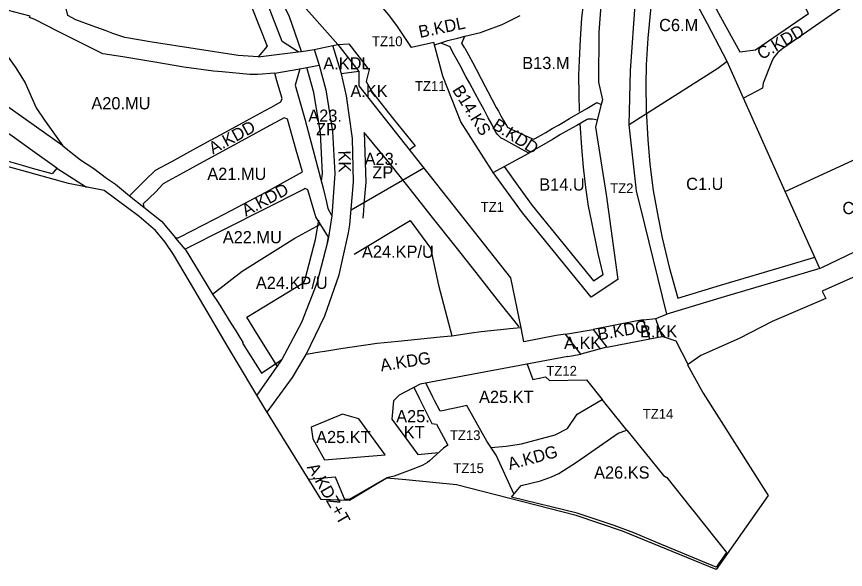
# Model space of a CAD drawing. Extents: x -292612 to -290407, y 29458 to 30862.
# Drawn here: x -292209 to -291531, y 29458 to 29911 of the extents above; entities that cross this region are included whole.
import ezdxf

# ---------------------------------------------------------------- set-up
doc = ezdxf.new("R2010")
doc.units = 0
for name, color, linetype in [('linie_rozgraniczajace', 7, 'Continuous'), ('linie_zabudowy_nieprzekraczalne', 7, 'Continuous'), ('linie_zabudowy_obowiazujace', 7, 'Continuous'), ('oznaczenia_przeznaczen', 7, 'Continuous')]:
    doc.layers.add(name, color=color, linetype=linetype)

msp = doc.modelspace()

# ---------------------------------------------------------------- linework, layer by layer
at = {"layer": 'linie_rozgraniczajace'}
for p, q in [((-291812.1, 29904.25), (-291797.36, 29911.59)), ((-291829.65, 29897.7), (-291825.32, 29899.4)), ((-291825.32, 29899.4), (-291812.1, 29904.25)), ((-291844.92, 29889.06), (-291842.53, 29894.59)), ((-291842.53, 29894.59), (-291829.65, 29897.7)), ((-291965.84, 29883.72), (-291950.47, 29887.05)), ((-291867.39, 29887.64), (-291862.03, 29889.28)), ((-291862.03, 29889.28), (-291854.9, 29886.32)), ((-291851.23, 29879.5), (-291854.9, 29886.32)), ((-291842.44, 29884.74), (-291844.92, 29889.06)), ((-292011.57, 29877.83), (-291978.9, 29881.84)), ((-291975.93, 29882.22), (-291965.84, 29883.72)), ((-291614.65, 29844.03), (-291628.04, 29874)), ((-291997.89, 29864.27), (-291977.45, 29868.02)), ((-291977.45, 29868.02), (-291961.66, 29870.95)), ((-291929.15, 29865.82), (-291943.39, 29863.71)), ((-292171.12, 29805.01), (-292230.27, 29846.8)), ((-291580.53, 29767.68), (-291614.65, 29844.03)), ((-292204.65, 29784.63), (-292279.28, 29805.58)), ((-291819.45, 29783.2), (-291790.26, 29798.92)), ((-292166.46, 29774.12), (-292204.65, 29784.63)), ((-292176.13, 29786.65), (-292151.9, 29771.21)), ((-292137.34, 29768.3), (-292166.46, 29774.12)), ((-292108.8, 29747.12), (-292137.34, 29768.3)), ((-292116.7, 29764.04), (-292105.11, 29754.82)), ((-291552.37, 29704.65), (-291580.53, 29767.68)), ((-292095.49, 29735.63), (-292108.8, 29747.12)), ((-291419.51, 29744.27), (-291550.37, 29686.12)), ((-292087.4, 29726.18), (-292095.49, 29735.63)), ((-292071.14, 29720.41), (-292079.07, 29729.79)), ((-291954.76, 29726.01), (-291953.92, 29730.34)), ((-292080.74, 29716.04), (-292087.4, 29726.18)), ((-292063.2, 29686.48), (-292080.74, 29716.04)), ((-292035.67, 29639.74), (-292063.2, 29686.48)), ((-291550.37, 29686.12), (-291547.48, 29680.03)), ((-291547.48, 29680.03), (-291591.32, 29661.25)), ((-291696.77, 29662.51), (-291686.12, 29663.74)), ((-291591.32, 29661.25), (-291618.23, 29647.39)), ((-291760.33, 29650.81), (-291737.71, 29654.77)), ((-291691.29, 29647.01), (-291681.18, 29648.88)), ((-291618.23, 29647.39), (-291649.65, 29633.45)), ((-292006.18, 29590.14), (-292035.67, 29639.74)), ((-291726.59, 29640.12), (-291747.55, 29634.63)), ((-291992.84, 29629.15), (-291992.27, 29630.09)), ((-291649.65, 29633.45), (-291660.43, 29625.85)), ((-291660.43, 29625.85), (-291647.77, 29602.64)), ((-291742.98, 29613.44), (-291730.19, 29597.44)), ((-291647.77, 29602.64), (-291594.44, 29518.94)), ((-291710.19, 29572.46), (-291730.19, 29597.44)), ((-291960, 29515.62), (-292006.18, 29590.14)), ((-291912.73, 29529.27), (-291936.78, 29514.91)), ((-291906.28, 29532.99), (-291912.73, 29529.27)), ((-291890.88, 29531.71), (-291906.28, 29532.99)), ((-291849.33, 29527.56), (-291890.88, 29531.71)), ((-291751.47, 29502.66), (-291849.33, 29527.56)), ((-291936.78, 29514.91), (-291960, 29515.62)), ((-291594.44, 29518.94), (-291636.96, 29458.4)), ((-291713.73, 29489.82), (-291751.47, 29502.66)), ((-291636.96, 29458.4), (-291713.73, 29489.82))]:
    msp.add_line(p, q, dxfattribs=at)
for points in [[(-292114.36, 30097.25), (-292083.21, 30056.76), (-292057.73, 30024.34), (-292038.64, 30000), (-292027.25, 29985.48), (-292000, 29950.73), (-291986.69, 29933.75), (-291946.41, 29887.93)], [(-291978.9, 29881.84), (-291991.76, 29890.16), (-292004.47, 29922.77), (-292020.82, 29953.71), (-292040.59, 29982.6), (-292063.52, 30009.04), (-292089.32, 30032.69), (-292097.85, 30039.41), (-292114.29, 30050.9), (-292134.97, 30069.53), (-292134, 30082.58), (-292121.07, 30092.24), (-292116.85, 30090.65)], [(-291975.93, 29882.22), (-291986.13, 29911.24), (-291999.65, 29938.08), (-292000.85, 29939.93), (-292019.3, 29969.25), (-292074.88, 30038.31), (-292089.02, 30055.89), (-292116.85, 30090.65)], [(-292166.99, 29911.62), (-292169.08, 29919.34), (-292154.75, 29958), (-292118.26, 30025.98), (-292105.47, 30028.88), (-292100.59, 30025.07), (-292075.06, 30002.23), (-292052.38, 29976.58), (-292032.83, 29948.45), (-292016.7, 29918.24), (-292004.2, 29886.35), (-292011.57, 29877.83)], [(-291669.49, 29987.68), (-291671.27, 29980.66), (-291633.48, 29910.49), (-291617.58, 29881.84), (-291604.81, 29883.45), (-291561.59, 29913.3), (-291592.04, 29971.03), (-291613.04, 30015.42), (-291620.76, 30015.91)], [(-291628.04, 29874), (-291644.01, 29904.73), (-291682.1, 29975.46), (-291688.74, 29976.95)], [(-291708.15, 29822.07), (-291707.18, 29866.32), (-291703.04, 29924.32), (-291698.38, 29961.89), (-291704.52, 29968.14)], [(-291729.07, 29948.78), (-291732.96, 29897.85), (-291733.22, 29856.93), (-291730.07, 29842.68), (-291731.09, 29838.65)], [(-291477.58, 29947.7), (-291488.85, 29948.52), (-291538.79, 29914.86), (-291582.58, 29884.55), (-291586.65, 29881.17), (-291590.07, 29876.95), (-291591.84, 29873.31), (-291598.51, 29856.15), (-291599.12, 29852.22), (-291614.65, 29844.03)], [(-292176.13, 29786.65), (-292196.11, 29800.91), (-292210.7, 29811.42), (-292226.79, 29822.79), (-292241.71, 29833.57), (-292257.21, 29844.57), (-292269.58, 29853.38), (-292281.3, 29861.8), (-292295.02, 29871.61), (-292309.25, 29881.48), (-292327.43, 29894.85), (-292343.8, 29906.62), (-292364.93, 29920.68), (-292373.24, 29925.15), (-292378.63, 29927), (-292388.33, 29930.59), (-292395.2, 29933), (-292403.59, 29934.7), (-292409.88, 29935.52), (-292417.09, 29936.06)], [(-291819.45, 29783.2), (-291820.74, 29785.22), (-291845.84, 29824.54), (-291860.59, 29861.86), (-291867.85, 29889.42), (-291886.03, 29885.5), (-291897.71, 29902.45), (-291904.57, 29912.13), (-291917.59, 29927.44), (-291924.51, 29934.99)], [(-291997.89, 29864.27), (-292011.86, 29863.38), (-292018.37, 29863.29), (-292040.84, 29865.39), (-292047.97, 29865.95), (-292072.31, 29869.28), (-292095.86, 29873.28), (-292122.04, 29877.72), (-292138.55, 29880.13), (-292175.49, 29898.85), (-292194.21, 29908.17), (-292198.39, 29909.92), (-292198.03, 29911.14), (-292216.69, 29915.79), (-292234.71, 29910.07), (-292238.43, 29904.69), (-292222.57, 29886.61), (-292209.52, 29868.85), (-292202.01, 29856.35), (-292193.02, 29835.97), (-292186.08, 29825.88), (-292171.12, 29805.01)], [(-292011.57, 29877.83), (-292027.9, 29878.97), (-292098.18, 29889.69), (-292120.57, 29893.65), (-292130.23, 29896.77), (-292135.79, 29898.9), (-292147.1, 29903), (-292160.49, 29907.99), (-292166.99, 29911.62)], [(-291862.03, 29889.28), (-291856.29, 29891.03), (-291847.39, 29893.41), (-291842.53, 29894.59)], [(-292004.27, 29587.05), (-291983.42, 29615.52), (-291972.23, 29634.18), (-291956.92, 29665.97), (-291945.31, 29699.29), (-291937.53, 29733.71), (-291936.49, 29740.42), (-291933.42, 29775.57), (-291934.36, 29810.85), (-291939.27, 29845.79), (-291943.39, 29863.71), (-291950.47, 29887.05)], [(-291950.47, 29887.05), (-291946.41, 29887.93), (-291929.15, 29865.82)], [(-291946.41, 29887.93), (-291937.46, 29888.27), (-291922.27, 29869), (-291921.77, 29868.36), (-291920.76, 29867.25), (-291923.26, 29857.68), (-291918.01, 29848.67), (-291900.93, 29826.77), (-291883.11, 29805.03), (-291888, 29801.34)], [(-291965.84, 29883.72), (-291961.66, 29870.95), (-291956.29, 29850.65), (-291950.62, 29816.63), (-291948.92, 29782.19), (-291951.21, 29747.78), (-291953.92, 29730.34), (-291954.76, 29726.01), (-291963.52, 29692.65), (-291976.08, 29660.54), (-291992.27, 29630.09), (-291992.84, 29629.15), (-292012.55, 29600.85)], [(-291978.9, 29881.84), (-291975.93, 29882.22)], [(-291790.26, 29798.92), (-291796.13, 29802.18), (-291804.17, 29806.62), (-291810.79, 29810.26), (-291812.68, 29811.31), (-291813.97, 29812.34), (-291815.19, 29813.59), (-291816.09, 29814.6), (-291817.13, 29816.25), (-291818.48, 29818.68), (-291820.58, 29822.61), (-291823.36, 29827.72), (-291826.84, 29834.26), (-291830.56, 29841.08), (-291834.14, 29847.84), (-291838.74, 29856.35), (-291841.6, 29861.78), (-291846.37, 29870.59), (-291851.23, 29879.5)], [(-291842.44, 29884.74), (-291839.51, 29879.32), (-291836.02, 29872.73), (-291833.31, 29867.58), (-291829.23, 29859.69), (-291825.97, 29853.55), (-291823.67, 29849.25), (-291820.34, 29843.21), (-291816.8, 29836.42), (-291815.08, 29833.29), (-291813, 29829.38), (-291810.91, 29825.67), (-291809.04, 29822.4), (-291808.31, 29821.18), (-291807.96, 29820.46), (-291807.84, 29820.32), (-291807.45, 29820.01), (-291806.67, 29819.55), (-291805.25, 29818.9), (-291801.51, 29817.18), (-291797.37, 29815.32), (-291793.93, 29813.74), (-291790.74, 29812.33), (-291787.8, 29810.98), (-291786.88, 29810.59), (-291786.22, 29810.28), (-291784.97, 29810.97), (-291780.65, 29813.47), (-291776.32, 29815.97), (-291771.01, 29819.06), (-291766.05, 29821.96), (-291763.32, 29823.53), (-291757.02, 29827.18), (-291749.88, 29831.34), (-291742.83, 29835.44), (-291734.64, 29840.26), (-291731.09, 29838.65)], [(-291628.04, 29874), (-291635.67, 29868.3), (-291708.15, 29822.07)], [(-291977.45, 29868.02), (-291981.2, 29854.6), (-291973.13, 29826.06), (-291958.14, 29769.24), (-291955.73, 29758.97), (-291954.61, 29753.62), (-291951.54, 29748.34), (-291951.21, 29747.78)], [(-291929.15, 29865.82), (-291929.2, 29854.09), (-291869.76, 29778.84)], [(-292116.7, 29764.04), (-292103.92, 29776.85), (-292095.34, 29785.07), (-292082.05, 29792.17), (-292067.31, 29800.29), (-292053.39, 29807.89), (-292053.39, 29807.89), (-292038.88, 29815.71), (-292024.24, 29823.84), (-292009.25, 29831.95), (-292001.11, 29836.4), (-291992.93, 29840.88), (-291991.92, 29843.6), (-291996.15, 29858), (-291997.89, 29864.27)], [(-291731.09, 29838.65), (-291734.29, 29825.91)], [(-292079.07, 29729.79), (-292076.96, 29729.54), (-292063.98, 29736.11), (-292057.76, 29739.43), (-292046.23, 29745.57), (-292046.23, 29745.57), (-292033.69, 29752.04), (-292019.21, 29759.66), (-292004.74, 29767.3), (-291990.64, 29775.1), (-291975.14, 29783.58), (-291980.34, 29801.42), (-291987.38, 29826.71), (-291990.14, 29827.97), (-292004.85, 29819.86), (-292018.92, 29812.27), (-292052.84, 29793.77), (-292059.35, 29790.22), (-292072.88, 29782.79), (-292084.75, 29776.28), (-292089.08, 29773.91), (-292095.52, 29767.12), (-292105.4, 29757.58), (-292105.11, 29754.82)], [(-291734.29, 29825.91), (-291735.7, 29820.33), (-291726.98, 29765.04), (-291717.33, 29695.68), (-291739.36, 29681.25), (-291795.41, 29750), (-291819.45, 29783.2)], [(-291734.29, 29825.91), (-291736.55, 29826.42), (-291738.11, 29826.64), (-291739.37, 29826.79), (-291740.41, 29826.83), (-291741.83, 29826.67), (-291742.48, 29826.52), (-291742.93, 29826.29), (-291750.94, 29821.67), (-291760.46, 29816.32), (-291764.18, 29814.08), (-291770.98, 29810.15), (-291778.04, 29805.99), (-291785.63, 29801.62), (-291790.26, 29798.92)], [(-292176.13, 29786.65), (-292179.9, 29782), (-292195.99, 29786.46), (-292204.16, 29788.73), (-292219.53, 29793.15), (-292222.85, 29794.21), (-292241.54, 29800.15), (-292247.59, 29801.03), (-292256.25, 29803.2), (-292259.91, 29804.26), (-292277.27, 29809.28), (-292284.64, 29811.13), (-292292.09, 29812.37), (-292306.82, 29815.42), (-292322.02, 29816.42), (-292337.28, 29817.73), (-292352.2, 29818.98), (-292358.98, 29819.79), (-292367.32, 29820.24), (-292383.03, 29819.54), (-292400.19, 29817.82), (-292414.25, 29816.53)], [(-291677.39, 29667.14), (-291695.46, 29740.67), (-291702.05, 29768.09), (-291708.15, 29822.07)], [(-292171.12, 29805.01), (-292156.78, 29793.44), (-292145.99, 29786.44), (-292135.51, 29778.61), (-292128.07, 29773.51), (-292116.7, 29764.04)], [(-291580.53, 29767.68), (-291512.04, 29799.08)], [(-291935.42, 29752.67), (-291876.07, 29786.84)], [(-291869.76, 29778.84), (-291805.12, 29697.02), (-291796.65, 29656.06)], [(-291953.92, 29730.34), (-291964.34, 29746.73), (-291965.24, 29749.6), (-291970.8, 29768.85), (-291973.12, 29769.91), (-291974.02, 29769.41), (-292071.14, 29720.41)], [(-292105.11, 29754.82), (-292090.53, 29743.24), (-292079.07, 29729.79)], [(-292048.73, 29683.68), (-292024.53, 29702.45), (-291981.57, 29729.3), (-291960.57, 29740.8)], [(-291483.76, 29737.37), (-291550.77, 29705.13), (-291552.37, 29704.65)], [(-292071.14, 29720.41), (-292048.73, 29683.68), (-292044.31, 29676.65)], [(-291552.37, 29704.65), (-291600, 29690.42), (-291630.47, 29681.32), (-291677.39, 29667.14)], [(-292044.31, 29676.65), (-292033.8, 29659.92), (-292029.72, 29653.67), (-292026.47, 29648.06), (-292024.1, 29644.26), (-292024.25, 29643.56), (-292008.79, 29618.94), (-291992.27, 29630.09)], [(-291703.01, 29661.53), (-291737.71, 29654.77), (-291726.49, 29640.12), (-291691.29, 29647.01), (-291696.77, 29662.51), (-291703.01, 29661.53)], [(-291660.02, 29626.14), (-291669.8, 29645.12), (-291681.18, 29648.88), (-291685.44, 29660.92), (-291686.48, 29663.6), (-291677.39, 29667.14)], [(-291796.65, 29656.06), (-291803.02, 29655.4), (-291829.08, 29652.83), (-291837.03, 29651.81), (-291853.02, 29649.19), (-291853.74, 29649.26), (-291862.82, 29648.53), (-291897.06, 29644.96), (-291914.15, 29643.22), (-291943.97, 29638.91), (-291957.01, 29636.79), (-291961.13, 29636.07), (-291972.23, 29634.18)], [(-291758.32, 29632.61), (-291747.55, 29634.63), (-291760.33, 29650.81), (-291767.71, 29649.67), (-291794.21, 29644.68), (-291796.58, 29656.07), (-291796.65, 29656.06)], [(-291758.32, 29632.61), (-291879.17, 29609.88), (-291896.12, 29601.01), (-291900.88, 29596.32), (-291902.08, 29581.24), (-291880.98, 29552.53), (-291864.05, 29554.09)], [(-291791.48, 29626.37), (-291786.9, 29613.88), (-291776.57, 29616.06), (-291773.21, 29613.01), (-291742.98, 29613.44)], [(-291802.63, 29520.13), (-291802.54, 29520.31), (-291816.93, 29551.77), (-291824.49, 29563.3), (-291827.97, 29569.73), (-291841.02, 29592.38), (-291849.31, 29590.62), (-291856.16, 29589.17), (-291859.44, 29588.47), (-291862.67, 29587.78), (-291862.79, 29587.75), (-291867.22, 29596.56), (-291868.68, 29599.46), (-291869.86, 29601.8), (-291874.39, 29610.78)], [(-291884.11, 29607.3), (-291880.18, 29599.34), (-291879.79, 29598.56), (-291877.62, 29594.17), (-291869.54, 29577.82), (-291865.57, 29577.32), (-291856.37, 29560.03), (-291860.05, 29557.72), (-291871.46, 29547.36), (-291873, 29545.97), (-291876.85, 29543.58), (-291882.84, 29541.21), (-291900.3, 29534.62), (-291906.36, 29533.39), (-291937.01, 29515.61), (-291940.35, 29515.48)], [(-291821.05, 29558.05), (-291808.76, 29559.19), (-291796.2, 29561.27), (-291768.74, 29568.53), (-291758.71, 29573.58), (-291750.67, 29585.4), (-291730.19, 29597.44)], [(-291907.66, 29552.25), (-291929.31, 29581.71), (-291942.41, 29585.41), (-291968.21, 29574.89), (-291966.69, 29565.34), (-291957.16, 29548.19), (-291907.66, 29552.25)], [(-291628.62, 29472.16), (-291637.05, 29460.38), (-291685.09, 29480.18), (-291704.31, 29488.21), (-291720.53, 29494.22), (-291750.78, 29504.38), (-291804.32, 29517.46), (-291803.39, 29518.85), (-291796.43, 29527.03), (-291780.72, 29530.79), (-291771.62, 29534.14), (-291765.71, 29536.91), (-291751.32, 29546.04), (-291717.29, 29569.98), (-291710.19, 29572.46)], [(-291710.19, 29572.46), (-291679.97, 29535.13), (-291677.32, 29533.69), (-291657.39, 29508.63), (-291654.91, 29505.48), (-291628.62, 29472.16)], [(-291940.38, 29514.78), (-291948.38, 29533.77), (-291970.19, 29532.05)], [(-291940.38, 29514.78), (-291960, 29515.62), (-291970.19, 29532.05)]]:
    msp.add_lwpolyline(points, dxfattribs=at)
at = {"layer": 'linie_zabudowy_nieprzekraczalne'}
for points in [[(-291932.88, 29716.19), (-291887.27, 29743.77), (-291870.63, 29721.33), (-291863.92, 29691.02), (-291853.18, 29649.44)], [(-291995.79, 29624.45), (-292012.52, 29651.52), (-292020.67, 29664.64), (-291974.07, 29693.13)]]:
    msp.add_lwpolyline(points, dxfattribs=at)
at = {"layer": 'linie_zabudowy_obowiazujace'}
for points in [[(-291681.39, 29972.33), (-291685.15, 29954.07), (-291688.33, 29934.01), (-291690.73, 29915.96), (-291692.92, 29893.15), (-291694.23, 29871.17), (-291694.5, 29854.67), (-291694.32, 29834.01), (-291693.03, 29810.03), (-291691.16, 29790.03), (-291688.57, 29768.51), (-291684.49, 29746.38), (-291681.15, 29729.67), (-291675.36, 29705.72), (-291668.28, 29680.34), (-291633.35, 29690.9), (-291578.24, 29707.36), (-291556.48, 29713.86)], [(-291748.86, 29832.89), (-291749.14, 29847.16), (-291749.27, 29862.73), (-291748.9, 29874.71), (-291748.03, 29892.08), (-291746.76, 29909.36), (-291744.41, 29930), (-291742.71, 29942.85)], [(-291959.58, 29776.2), (-291958.93, 29782.28), (-291960.57, 29815.56), (-291966.08, 29848.55), (-291971.67, 29869.09)], [(-291810.48, 29788.05), (-291799.02, 29772.04), (-291787.48, 29756.1), (-291762.39, 29725.33), (-291737.3, 29694.55), (-291729.55, 29699.63), (-291733.59, 29716.89), (-291739.08, 29743.94), (-291741.44, 29755.67), (-291743.52, 29770.82), (-291745.56, 29787.43), (-291746.98, 29803.66), (-291748.35, 29823.24)], [(-291798.15, 29656.75), (-291815.77, 29679.05), (-291833.28, 29701.22), (-291849.69, 29721.99), (-291868.91, 29746.32), (-291888.14, 29770.67), (-291903.88, 29790.59), (-291924.96, 29815.86), (-291923.41, 29775.27), (-291924.98, 29757.25), (-291925.47, 29751.68), (-291925.99, 29745.66)], [(-291974.07, 29693.13), (-291973.04, 29695.76), (-291964.52, 29728.23), (-291961.89, 29744.18)]]:
    msp.add_lwpolyline(points, dxfattribs=at)

# ---------------------------------------------------------------- texts
at = {"layer": 'oznaczenia_przeznaczen'}
for s, rotation, p in [('B.KDL', 11.79343, (-291879.21, 29893.14)), ('C.KDD', 30.56084, (-291599.82, 29874.96)), ('B14.KS', 302.10626, (-291853.15, 29850.65)), ('A.KDD', 28.70567, (-292048.5, 29797.8)), ('B.KDD', 327.48809, (-291820.9, 29819.55)), ('KK', 270.84785, (-291945.88, 29801.04)), ('A.KDD', 28.16853, (-292021.54, 29746.86)), ('C2.KU', 358.47279, (-291533.98, 29749.21)), ('B.KDG', 9.84526, (-291733.13, 29645.76)), ('A.KDG', 8.91653, (-291910.89, 29620.39)), ('A.KDG', 15.14098, (-291805.89, 29539.7)), ('A.KDZ+T', 299.79113, (-291971.86, 29542.02))]:
    msp.add_text(s, height=10, rotation=rotation, dxfattribs=at).set_placement(p)
for s, height, p in [('C6.M', 10, (-291683.66, 29898.75)), ('TZ10', 8, (-291918.43, 29886.45)), ('A.KDL', 10, (-291958.24, 29867.41)), ('B13.M', 10, (-291795.57, 29867.73)), ('A.KK', 10, (-291936.08, 29844.76)), ('TZ11', 8, (-291883.25, 29849.88)), ('A20.MU', 10, (-292147.87, 29834.76)), ('A23.', 10, (-291970.51, 29824.61)), ('ZP', 10, (-291964.2, 29813.61)), ('A23.', 10, (-291924.45, 29789.26)), ('A21.MU', 10, (-292053.08, 29777.07)), ('ZP', 10, (-291918.14, 29778.26)), ('B14.U', 10, (-291781.66, 29768.34)), ('C1.U', 10, (-291661.58, 29768.82)), ('TZ2', 8, (-291723.68, 29766.22)), ('TZ1', 8, (-291829.55, 29750.93)), ('A22.MU', 10, (-292040.42, 29725.23)), ('A24.KP/U', 10, (-291926.61, 29713.36)), ('A24.KP/U', 10, (-292013.38, 29687.85)), ('B.KK', 10, (-291699.33, 29648.21)), ('A.KK', 10, (-291761.35, 29638.74)), ('TZ12', 8, (-291775.88, 29616.91)), ('A25.KT', 10, (-291830.93, 29594.59)), ('A25.', 10, (-291898.66, 29578.75)), ('TZ14', 8, (-291697, 29581.7)), ('KT', 10, (-291892.51, 29565.66)), ('A25.KT', 10, (-291964.11, 29561.71)), ('TZ13', 8, (-291854.72, 29564.23)), ('TZ15', 8, (-291851.94, 29537.21)), ('A26.KS', 10, (-291736.84, 29532.75))]:
    msp.add_text(s, height=height, dxfattribs=at).set_placement(p)

doc.saveas('drawing.dxf')
